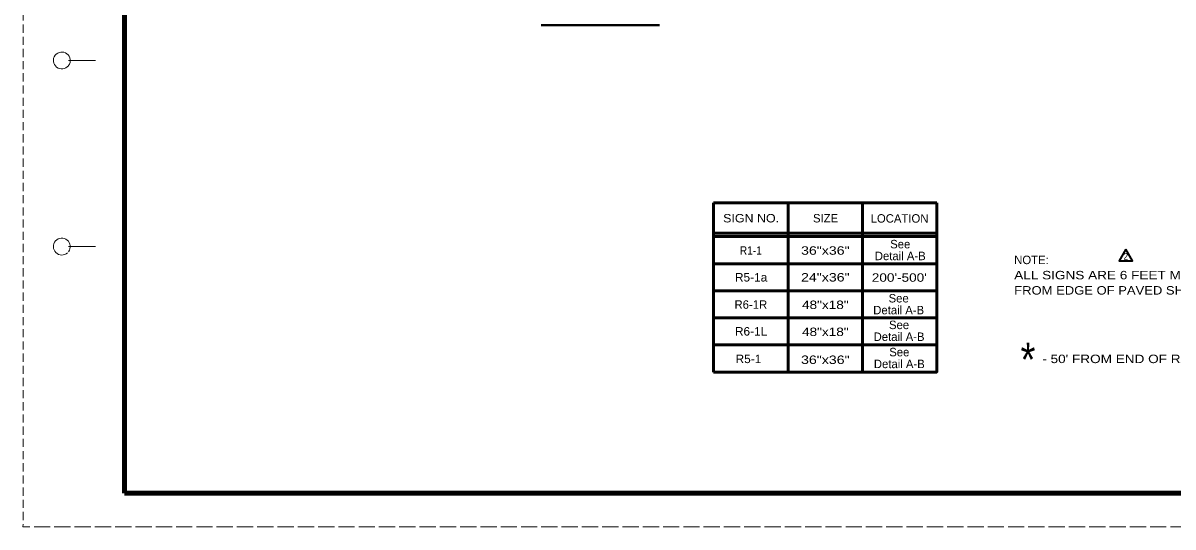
# Model space of a CAD drawing. Extents: x -133 to 547, y -328 to 112.
# Drawn here: x -133.4 to 206.7, y -328.3 to -179.4 of the extents above; entities that cross this region are included whole.
import ezdxf
from ezdxf.enums import TextEntityAlignment as Align

# ---------------------------------------------------------------- set-up
doc = ezdxf.new("R2010")
doc.units = 0
doc.header["$LTSCALE"] = 0.8
doc.linetypes.add('LONG_DASHED', pattern=[7.5, 6, -1.5])
doc.linetypes.add('MEDIUM_DASHED', pattern=[4.5, 3, -1.5])
doc.layers.add('1', color=7, linetype='Continuous', lineweight=35)
doc.layers.add('61', color=7, linetype='Continuous', lineweight=35)

msp = doc.modelspace()

# ---------------------------------------------------------------- linework, layer by layer
at = {"layer": '1', "linetype": 'MEDIUM_DASHED', "lineweight": 13}
msp.add_line((-133.3064, 111.6965), (-133.3664, -328.3435), dxfattribs=at)
at = {"layer": '1', "lineweight": 40}
msp.add_line((19.8495, -180.061), (54.8124, -180.061), dxfattribs=at)
at = {"layer": '1', "lineweight": 53}
for p, q in [((70.8353, -241.5588), (70.8353, -232.5588)), ((92.8353, -282.5587), (92.8353, -232.5588)), ((114.8353, -282.5587), (114.8353, -232.5588)), ((70.8353, -241.5588), (136.8353, -241.5588)), ((70.8353, -241.5588), (70.8353, -242.5588)), ((70.8353, -242.5588), (136.8353, -242.5588)), ((70.8353, -250.5588), (70.8353, -242.5588)), ((70.8353, -250.5588), (136.8353, -250.5588)), ((70.8353, -258.5587), (70.8353, -250.5588)), ((70.8353, -258.5587), (136.8353, -258.5587)), ((70.8353, -266.5587), (70.8353, -258.5587)), ((70.8353, -266.5587), (136.8353, -266.5587)), ((70.8353, -274.5587), (136.8353, -274.5587))]:
    msp.add_line(p, q, dxfattribs=at)
for points in [[(136.8353, -232.5588), (136.8353, -282.5587), (70.8353, -282.5587)], [(70.8353, -232.5588), (92.8353, -232.5588), (114.8353, -232.5588), (136.8353, -232.5588)], [(70.8353, -282.5587), (70.8353, -274.5587), (70.8353, -266.5587)]]:
    msp.add_lwpolyline(points, dxfattribs=at)
at = {"layer": '1'}
msp.add_lwpolyline([(192.7412, -246.2906), (190.7412, -249.7547), (194.7412, -249.7547)], close=True, dxfattribs=at)
at = {"layer": '61', "lineweight": 13}
for p, q in [((-119.8864, -190.4835), (-111.8864, -190.4835)), ((-119.8664, -245.5035), (-111.8864, -245.5035))]:
    msp.add_line(p, q, dxfattribs=at)
at = {"layer": '61', "lineweight": 158}
msp.add_line((535.7536, -318.3435), (-103.3064, -318.3235), dxfattribs=at)
at = {"layer": '61', "linetype": 'LONG_DASHED', "lineweight": 13}
msp.add_line((546.6936, -328.3235), (-133.3664, -328.3435), dxfattribs=at)
at = {"layer": '61', "lineweight": 158}
msp.add_lwpolyline([(535.7336, 101.6965), (-103.3064, 101.6965), (-103.3064, -318.3235)], dxfattribs=at)
at = {"layer": '61', "lineweight": 13}
for centre, start, end in [((-121.8887, -190.5022), 322.67175, 321.71615), ((-121.8887, -245.5022), 323.13009, 312.31439)]:
    msp.add_arc(centre, 2.5, start, end, dxfattribs=at)

# ---------------------------------------------------------------- texts
at = {"layer": '1'}
for s, height, width, p in [('SIGN NO.', 2.5, 1.1, (81.9254, -238.3592)), ('R1-1', 2.5, 0.9, (81.8541, -247.9095)), ('36"x36"', 2.5, 1.25, (103.8699, -247.9095)), ('2', 2, 0.9, (192.7207, -249.3886)), ('R5-1a', 2.5, 1.05, (81.9255, -255.8207)), ('24"x36"', 2.5, 1.25, (103.8699, -255.8207)), ("200'-500'", 2.5, 1.2, (125.743, -255.8919)), ('48"x18"', 2.5, 1.2, (103.8699, -263.9456)), ('R6-1L', 2.5, 1.05, (81.9255, -271.7854)), ('48"x18"', 2.5, 1.2, (103.8699, -271.9279)), ('*', 10, 0.85, (163.7993, -283.8628)), ('R5-1', 2.5, 1.05, (81.1364, -279.925)), ('36"x36"', 2.5, 1.25, (103.8689, -280.1847)), ("- 50' FROM END OF RADIUS", 2.5, 1.2, (194.5919, -279.9243))]:
    msp.add_text(s, height=height, dxfattribs=dict(at, width=width)).set_placement(p, align=Align.CENTER)
for s, p in [('SIZE', (103.9411, -238.3592)), ('LOCATION', (125.8142, -238.4305)), ('See', (126.028, -246.017)), ('Detail A-B', (126.028, -249.517)), ('R6-1R', (81.8541, -263.8743)), ('See', (125.558, -262.0039)), ('Detail A-B', (125.558, -265.5039)), ('See', (125.6755, -269.8798)), ('Detail A-B', (125.6755, -273.3798)), ('See', (125.7471, -277.917)), ('Detail A-B', (125.7471, -281.417))]:
    msp.add_text(s, height=2.5, dxfattribs=at).set_placement(p, align=Align.CENTER)
msp.add_text('NOTE:', height=2.5, dxfattribs=at).set_placement((159.7242, -250.6795))
for s, width, p in [('ALL SIGNS ARE 6 FEET MINIMUM DISTANCE', 1.2, (159.7242, -255.1795)), ('FROM EDGE OF PAVED SHOULDER.', 1.15, (159.7242, -259.6795))]:
    msp.add_text(s, height=2.5, dxfattribs=dict(at, width=width)).set_placement(p)

doc.saveas('drawing.dxf')
